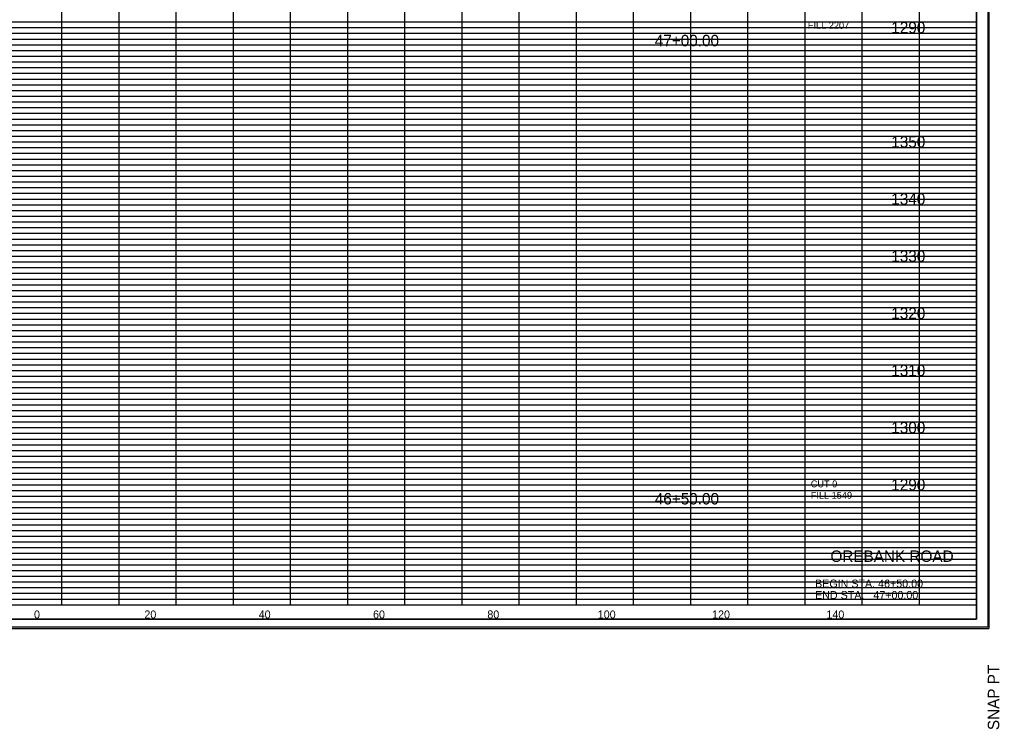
# Model space of a CAD drawing. Extents: x 980 to 1324, y 978 to 2847.
# Drawn here: x 1152.6 to 1324, y 2058.2 to 2182.4 of the extents above; entities that cross this region are included whole.
import ezdxf

# ---------------------------------------------------------------- set-up
doc = ezdxf.new("R2010")
doc.units = 0
for name, color, linetype in [('DESIGN - SHEET - Corner Text', 7, 'Continuous'), ('DESIGN - SHEET - Light Grid', 7, 'Continuous'), ('DESIGN - SHEET - Linework', 7, 'Continuous'), ('DESIGN - SHEET - Plot Shape', 7, 'Continuous'), ('DESIGN - TYPICAL - Text', 7, 'Continuous')]:
    doc.layers.add(name, color=color, linetype=linetype)

# ---------------------------------------------------------------- blocks, each defined once
blk = doc.blocks.new('XSTSHT')
at = {"layer": 'DESIGN - SHEET - Light Grid'}
for p, q in [((8, 10.2), (16, 10.2)), ((16, 10.2), (24, 10.2)), ((24, 10.2), (32, 10.2)), ((8, 10.1), (16, 10.1)), ((16, 10.1), (24, 10.1)), ((24, 10.1), (32, 10.1)), ((8, 9.9), (16, 9.9)), ((8, 9.8), (16, 9.8)), ((16, 9.9), (24, 9.9)), ((16, 9.8), (24, 9.8)), ((24, 9.9), (32, 9.9)), ((24, 9.8), (32, 9.8)), ((8, 9.7), (16, 9.7)), ((8, 9.6), (16, 9.6)), ((16, 9.7), (24, 9.7)), ((16, 9.6), (24, 9.6)), ((24, 9.7), (32, 9.7)), ((24, 9.6), (32, 9.6)), ((8, 9.5), (16, 9.5)), ((16, 9.5), (24, 9.5)), ((24, 9.5), (32, 9.5)), ((8, 9.4), (16, 9.4)), ((8, 9.3), (16, 9.3)), ((16, 9.4), (24, 9.4)), ((16, 9.3), (24, 9.3)), ((24, 9.4), (32, 9.4)), ((24, 9.3), (32, 9.3)), ((8, 9.2), (16, 9.2)), ((8, 9.1), (16, 9.1)), ((16, 9.2), (24, 9.2)), ((16, 9.1), (24, 9.1)), ((24, 9.2), (32, 9.2)), ((24, 9.1), (32, 9.1)), ((8, 8.9), (16, 8.9)), ((8, 8.8), (16, 8.8)), ((16, 8.9), (24, 8.9)), ((16, 8.8), (24, 8.8)), ((24, 8.9), (32, 8.9)), ((24, 8.8), (32, 8.8)), ((8, 8.7), (16, 8.7)), ((8, 8.6), (16, 8.6)), ((16, 8.7), (24, 8.7)), ((16, 8.6), (24, 8.6)), ((24, 8.7), (32, 8.7)), ((24, 8.6), (32, 8.6)), ((8, 8.5), (16, 8.5)), ((8, 8.4), (16, 8.4)), ((16, 8.5), (24, 8.5)), ((16, 8.4), (24, 8.4)), ((24, 8.5), (32, 8.5)), ((24, 8.4), (32, 8.4)), ((8, 8.3), (16, 8.3)), ((16, 8.3), (24, 8.3)), ((24, 8.3), (32, 8.3)), ((8, 8.2), (16, 8.2)), ((8, 8.1), (16, 8.1)), ((16, 8.2), (24, 8.2)), ((16, 8.1), (24, 8.1)), ((24, 8.2), (32, 8.2)), ((24, 8.1), (32, 8.1)), ((8, 7.9), (16, 7.9)), ((16, 7.9), (24, 7.9)), ((24, 7.9), (32, 7.9)), ((8, 7.8), (16, 7.8)), ((16, 7.8), (24, 7.8)), ((24, 7.8), (32, 7.8)), ((8, 7.7), (16, 7.7)), ((8, 7.6), (16, 7.6)), ((16, 7.7), (24, 7.7)), ((16, 7.6), (24, 7.6)), ((24, 7.7), (32, 7.7)), ((24, 7.6), (32, 7.6)), ((8, 7.5), (16, 7.5)), ((8, 7.4), (16, 7.4)), ((16, 7.5), (24, 7.5)), ((16, 7.4), (24, 7.4)), ((24, 7.5), (32, 7.5)), ((24, 7.4), (32, 7.4)), ((8, 7.3), (16, 7.3)), ((8, 7.2), (16, 7.2)), ((16, 7.3), (24, 7.3)), ((16, 7.2), (24, 7.2)), ((24, 7.3), (32, 7.3)), ((24, 7.2), (32, 7.2)), ((8, 7.1), (16, 7.1)), ((16, 7.1), (24, 7.1)), ((24, 7.1), (32, 7.1)), ((8, 6.9), (16, 6.9)), ((16, 6.9), (24, 6.9)), ((24, 6.9), (32, 6.9)), ((8, 6.8), (16, 6.8)), ((8, 6.7), (16, 6.7)), ((16, 6.8), (24, 6.8)), ((16, 6.7), (24, 6.7)), ((24, 6.8), (32, 6.8)), ((24, 6.7), (32, 6.7)), ((8, 6.6), (16, 6.6)), ((16, 6.6), (24, 6.6)), ((24, 6.6), (32, 6.6)), ((8, 6.5), (16, 6.5)), ((8, 6.4), (16, 6.4)), ((16, 6.5), (24, 6.5)), ((16, 6.4), (24, 6.4)), ((24, 6.5), (32, 6.5)), ((24, 6.4), (32, 6.4)), ((8, 6.3), (16, 6.3)), ((8, 6.2), (16, 6.2)), ((16, 6.3), (24, 6.3)), ((16, 6.2), (24, 6.2)), ((24, 6.3), (32, 6.3)), ((24, 6.2), (32, 6.2)), ((8, 6.1), (16, 6.1)), ((16, 6.1), (24, 6.1)), ((24, 6.1), (32, 6.1)), ((8, 5.9), (16, 5.9)), ((16, 5.9), (24, 5.9)), ((24, 5.9), (32, 5.9)), ((8, 5.8), (16, 5.8)), ((8, 5.7), (16, 5.7)), ((16, 5.8), (24, 5.8)), ((16, 5.7), (24, 5.7)), ((24, 5.8), (32, 5.8)), ((24, 5.7), (32, 5.7)), ((8, 5.6), (16, 5.6)), ((8, 5.5), (16, 5.5)), ((16, 5.6), (24, 5.6)), ((16, 5.5), (24, 5.5)), ((24, 5.6), (32, 5.6)), ((24, 5.5), (32, 5.5)), ((8, 5.4), (16, 5.4)), ((16, 5.4), (24, 5.4)), ((24, 5.4), (32, 5.4)), ((8, 5.3), (16, 5.3)), ((8, 5.2), (16, 5.2)), ((16, 5.3), (24, 5.3)), ((16, 5.2), (24, 5.2)), ((24, 5.3), (32, 5.3)), ((24, 5.2), (32, 5.2)), ((8, 5.1), (16, 5.1)), ((16, 5.1), (24, 5.1)), ((24, 5.1), (32, 5.1)), ((8, 4.9), (16, 4.9)), ((8, 4.8), (16, 4.8)), ((16, 4.9), (24, 4.9)), ((16, 4.8), (24, 4.8)), ((24, 4.9), (32, 4.9)), ((24, 4.8), (32, 4.8)), ((8, 4.7), (16, 4.7)), ((16, 4.7), (24, 4.7)), ((24, 4.7), (32, 4.7)), ((8, 4.6), (16, 4.6)), ((8, 4.5), (16, 4.5)), ((16, 4.6), (24, 4.6)), ((16, 4.5), (24, 4.5)), ((24, 4.6), (32, 4.6)), ((24, 4.5), (32, 4.5)), ((8, 4.4), (16, 4.4)), ((8, 4.3), (16, 4.3)), ((16, 4.4), (24, 4.4)), ((16, 4.3), (24, 4.3)), ((24, 4.4), (32, 4.4)), ((24, 4.3), (32, 4.3)), ((8, 4.2), (16, 4.2)), ((16, 4.2), (24, 4.2)), ((24, 4.2), (32, 4.2)), ((8, 4.1), (16, 4.1)), ((16, 4.1), (24, 4.1)), ((24, 4.1), (32, 4.1)), ((8, 3.9), (16, 3.9)), ((8, 3.8), (16, 3.8)), ((16, 3.9), (24, 3.9)), ((16, 3.8), (24, 3.8)), ((24, 3.9), (32, 3.9)), ((24, 3.8), (32, 3.8)), ((8, 3.7), (16, 3.7)), ((8, 3.6), (16, 3.6)), ((16, 3.7), (24, 3.7)), ((16, 3.6), (24, 3.6)), ((24, 3.7), (32, 3.7)), ((24, 3.6), (32, 3.6)), ((8, 3.5), (16, 3.5)), ((16, 3.5), (24, 3.5)), ((24, 3.5), (32, 3.5)), ((8, 3.4), (16, 3.4)), ((8, 3.3), (16, 3.3)), ((16, 3.4), (24, 3.4)), ((16, 3.3), (24, 3.3)), ((24, 3.4), (32, 3.4)), ((24, 3.3), (32, 3.3)), ((8, 3.2), (16, 3.2)), ((8, 3.1), (16, 3.1)), ((16, 3.2), (24, 3.2)), ((16, 3.1), (24, 3.1)), ((24, 3.2), (32, 3.2)), ((24, 3.1), (32, 3.1)), ((8, 2.9), (16, 2.9)), ((8, 2.8), (16, 2.8)), ((16, 2.9), (24, 2.9)), ((16, 2.8), (24, 2.8)), ((24, 2.9), (32, 2.9)), ((24, 2.8), (32, 2.8)), ((8, 2.7), (16, 2.7)), ((8, 2.6), (16, 2.6)), ((16, 2.7), (24, 2.7)), ((16, 2.6), (24, 2.6)), ((24, 2.7), (32, 2.7)), ((24, 2.6), (32, 2.6)), ((8, 2.5), (16, 2.5)), ((8, 2.4), (16, 2.4)), ((16, 2.5), (24, 2.5)), ((16, 2.4), (24, 2.4)), ((24, 2.5), (32, 2.5)), ((24, 2.4), (32, 2.4)), ((8, 2.3), (16, 2.3)), ((16, 2.3), (24, 2.3)), ((24, 2.3), (32, 2.3)), ((8, 2.2), (16, 2.2)), ((8, 2.1), (16, 2.1)), ((16, 2.2), (24, 2.2)), ((16, 2.1), (24, 2.1)), ((24, 2.2), (32, 2.2)), ((24, 2.1), (32, 2.1)), ((8, 1.9), (16, 1.9)), ((16, 1.9), (24, 1.9)), ((24, 1.9), (32, 1.9)), ((8, 1.8), (16, 1.8)), ((16, 1.8), (24, 1.8)), ((24, 1.8), (32, 1.8)), ((8, 1.7), (16, 1.7)), ((8, 1.6), (16, 1.6)), ((16, 1.7), (24, 1.7)), ((16, 1.6), (24, 1.6)), ((24, 1.7), (32, 1.7)), ((24, 1.6), (32, 1.6)), ((8, 1.5), (16, 1.5)), ((8, 1.4), (16, 1.4)), ((16, 1.5), (24, 1.5)), ((16, 1.4), (24, 1.4)), ((24, 1.5), (32, 1.5)), ((24, 1.4), (32, 1.4)), ((8, 1.3), (16, 1.3)), ((8, 1.2), (16, 1.2)), ((16, 1.3), (24, 1.3)), ((16, 1.2), (24, 1.2)), ((24, 1.3), (32, 1.3)), ((24, 1.2), (32, 1.2)), ((8, 1.1), (16, 1.1)), ((16, 1.1), (24, 1.1)), ((24, 1.1), (32, 1.1)), ((8, 0.9), (16, 0.9)), ((16, 0.9), (24, 0.9)), ((24, 0.9), (32, 0.9)), ((8, 0.8), (16, 0.8)), ((8, 0.7), (16, 0.7)), ((16, 0.8), (24, 0.8)), ((16, 0.7), (24, 0.7)), ((24, 0.8), (32, 0.8)), ((24, 0.7), (32, 0.7)), ((8, 0.6), (16, 0.6)), ((16, 0.6), (24, 0.6)), ((24, 0.6), (32, 0.6)), ((8, 0.5), (16, 0.5)), ((8, 0.4), (16, 0.4)), ((16, 0.5), (24, 0.5)), ((16, 0.4), (24, 0.4)), ((24, 0.5), (32, 0.5)), ((24, 0.4), (32, 0.4)), ((8, 0.3), (16, 0.3)), ((8, 0.2), (16, 0.2)), ((16, 0.3), (24, 0.3)), ((16, 0.2), (24, 0.2)), ((24, 0.3), (32, 0.3)), ((24, 0.2), (32, 0.2)), ((8, 0.1), (16, 0.1)), ((16, 0.1), (24, 0.1)), ((24, 0.1), (32, 0.1))]:
    blk.add_line(p, q, dxfattribs=at)
at = {"layer": 'DESIGN - SHEET - Linework'}
for p, q in [((32.217, 21.414), (32.217, -0.414)), ((16, 0), (16, 21)), ((17, 0), (17, 21)), ((18, 0), (18, 21)), ((19, 0), (19, 21)), ((20, 0), (20, 21)), ((21, 0), (21, 21)), ((22, 0), (22, 21)), ((23, 0), (23, 21)), ((24, 0), (24, 21)), ((25, 0), (25, 21)), ((26, 0), (26, 21)), ((27, 0), (27, 21)), ((28, 0), (28, 20)), ((29, 0), (29, 20)), ((30, 0), (30, 20)), ((31, 0), (31, 20)), ((0, 10), (32, 10)), ((0, 9), (32, 9)), ((0, 8), (32, 8)), ((0, 7), (32, 7)), ((0, 6), (32, 6)), ((0, 5), (32, 5)), ((0, 4), (32, 4)), ((0, 3), (32, 3)), ((0, 2), (32, 2)), ((0, 1), (32, 1)), ((-1.823, -0.414), (32.217, -0.414))]:
    blk.add_line(p, q, dxfattribs=at)
blk.add_lwpolyline([(0, 21), (0, 0), (32, 0), (32, 21), (0, 21)], dxfattribs=at)
at = {"layer": 'DESIGN - SHEET - Plot Shape'}
for points in [[(-1.803, 21.394), (32.197, 21.394), (32.197, -0.394), (-1.803, -0.394)], [(-0.85, 21), (32, 21), (32, -0.25), (-0.85, -0.25)]]:
    blk.add_lwpolyline(points, close=True, dxfattribs=at)
at = {"layer": 'DESIGN - SHEET - Corner Text'}
blk.add_text('SNAP PT  ', height=0.2, rotation=90, dxfattribs=at).set_placement((32.397, -2.194))

msp = doc.modelspace()

# ---------------------------------------------------------------- linework, layer by layer
at = {"layer": 'DESIGN - SHEET - Plot Shape'}
msp.add_lwpolyline([(991.5, 2077.5), (1320, 2077.5), (1320, 2290), (991.5, 2290)], close=True, dxfattribs=at)

# ---------------------------------------------------------------- block references
at = {"layer": 'DESIGN - SHEET - Plot Shape', "xscale": 10, "yscale": 10}
msp.add_blockref('XSTSHT', (1000, 2080), dxfattribs=at)

# ---------------------------------------------------------------- texts
at = {"layer": 'DESIGN - SHEET - Corner Text'}
for s, height, p in [('OREBANK ROAD', 2, (1294.44, 2087.5)), ('BEGIN STA. 46+50.00', 1.4, (1291.75, 2083)), ('END STA.   47+00.00', 1.4, (1291.75, 2081))]:
    msp.add_text(s, height=height, dxfattribs=at).set_placement(p)
at = {"layer": 'DESIGN - TYPICAL - Text'}
for s, height, p in [('FILL 2207', 1.2, (1290.49, 2180.78)), ('     1290     ', 2, (1301.37, 2180)), ('     47+00.00     ', 2, (1260, 2177.73)), ('     1350     ', 2, (1301.37, 2160)), ('     1340     ', 2, (1301.37, 2150)), ('     1330     ', 2, (1301.37, 2140)), ('     1320     ', 2, (1301.37, 2130)), ('     1310     ', 2, (1301.37, 2120)), ('     1300     ', 2, (1301.37, 2110)), ('CUT 0', 1.2, (1291, 2100.55)), ('     1290     ', 2, (1301.37, 2100)), ('FILL 1549', 1.2, (1291, 2098.55)), ('     46+50.00     ', 2, (1260, 2097.55)), ('     0     ', 1.4, (1152.51, 2077.6)), ('     0     ', 1.4, (1152.51, 2077.6)), ('     20     ', 1.4, (1171.82, 2077.6)), ('     40     ', 1.4, (1191.82, 2077.6)), ('     60     ', 1.4, (1211.82, 2077.6)), ('     80     ', 1.4, (1231.82, 2077.6)), ('     100     ', 1.4, (1251.14, 2077.6)), ('     120     ', 1.4, (1271.14, 2077.6)), ('     140     ', 1.4, (1291.14, 2077.6))]:
    msp.add_text(s, height=height, dxfattribs=at).set_placement(p)

doc.saveas('drawing.dxf')
